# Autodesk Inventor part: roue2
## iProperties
Shininess: 64.0
Length Units: 11269
Angle Units: 11279
Time Units: 11290
Mass Units: 11283
Length Display Precision: 3
Angle Display Precision: 2
Compacted: True
Part Number: roue2
Document SubType Name: Modeling
Created: 2004-09
Material: Par défaut
Designer: Laurent
Density: 1 g/cm^3
Density: 0.0
Volumn: 0.0
Area: 0.0
PropertySet Name: Model Information
Control State: 0
Master: False
Checked Out: False
Author: Laurent
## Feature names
1. Extrusion1
2. Extrusion2
3. Extrusion3
